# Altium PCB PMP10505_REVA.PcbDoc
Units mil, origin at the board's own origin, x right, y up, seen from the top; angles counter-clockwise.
Board outline 2750 x 2200 mil, 2 copper layers (Top Layer, Bottom Layer), stack 62 mil thick; 73 components, 28 nets, 117 pads, 15 vias.
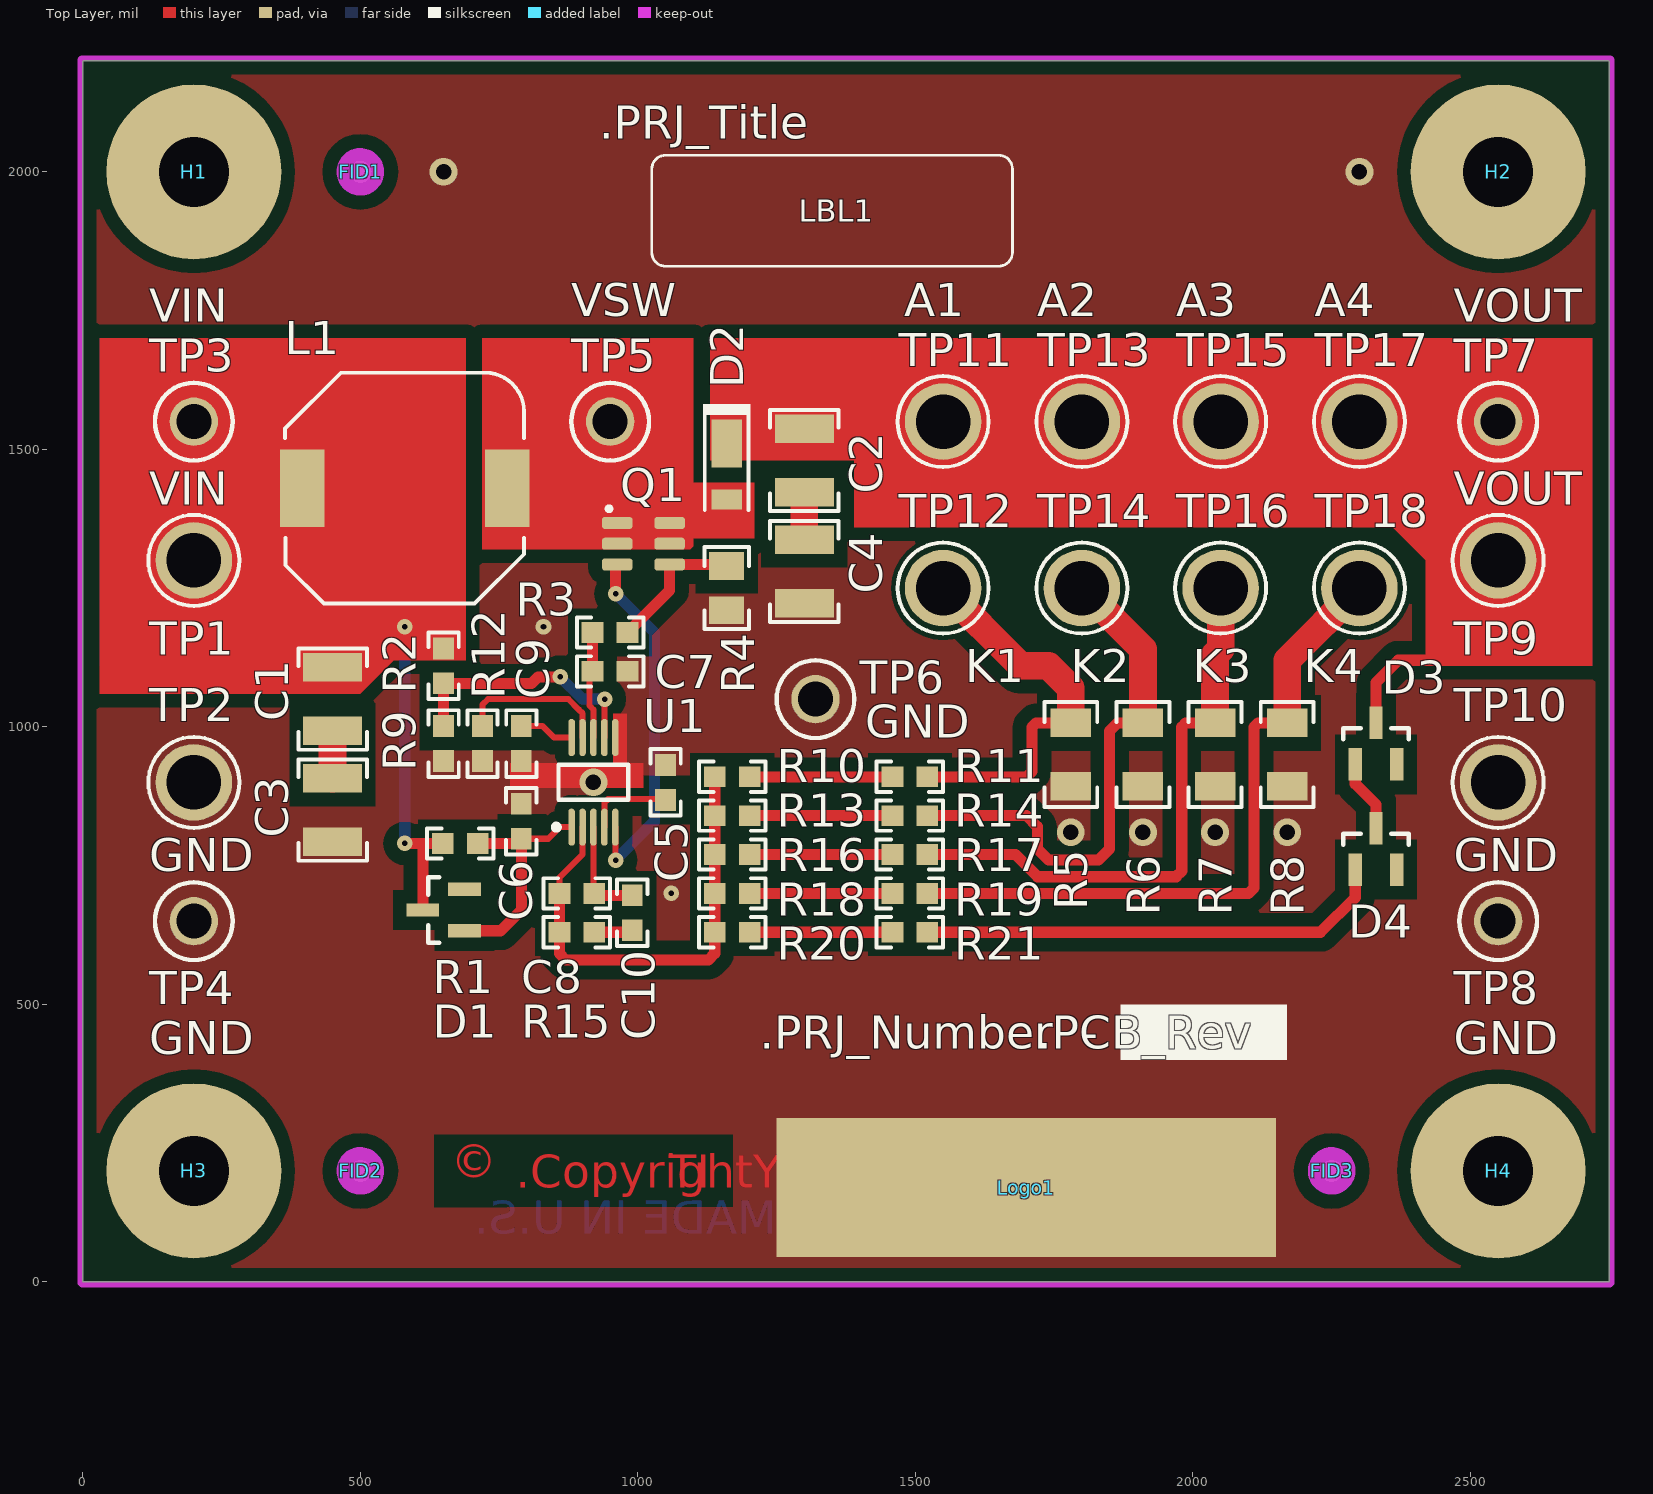
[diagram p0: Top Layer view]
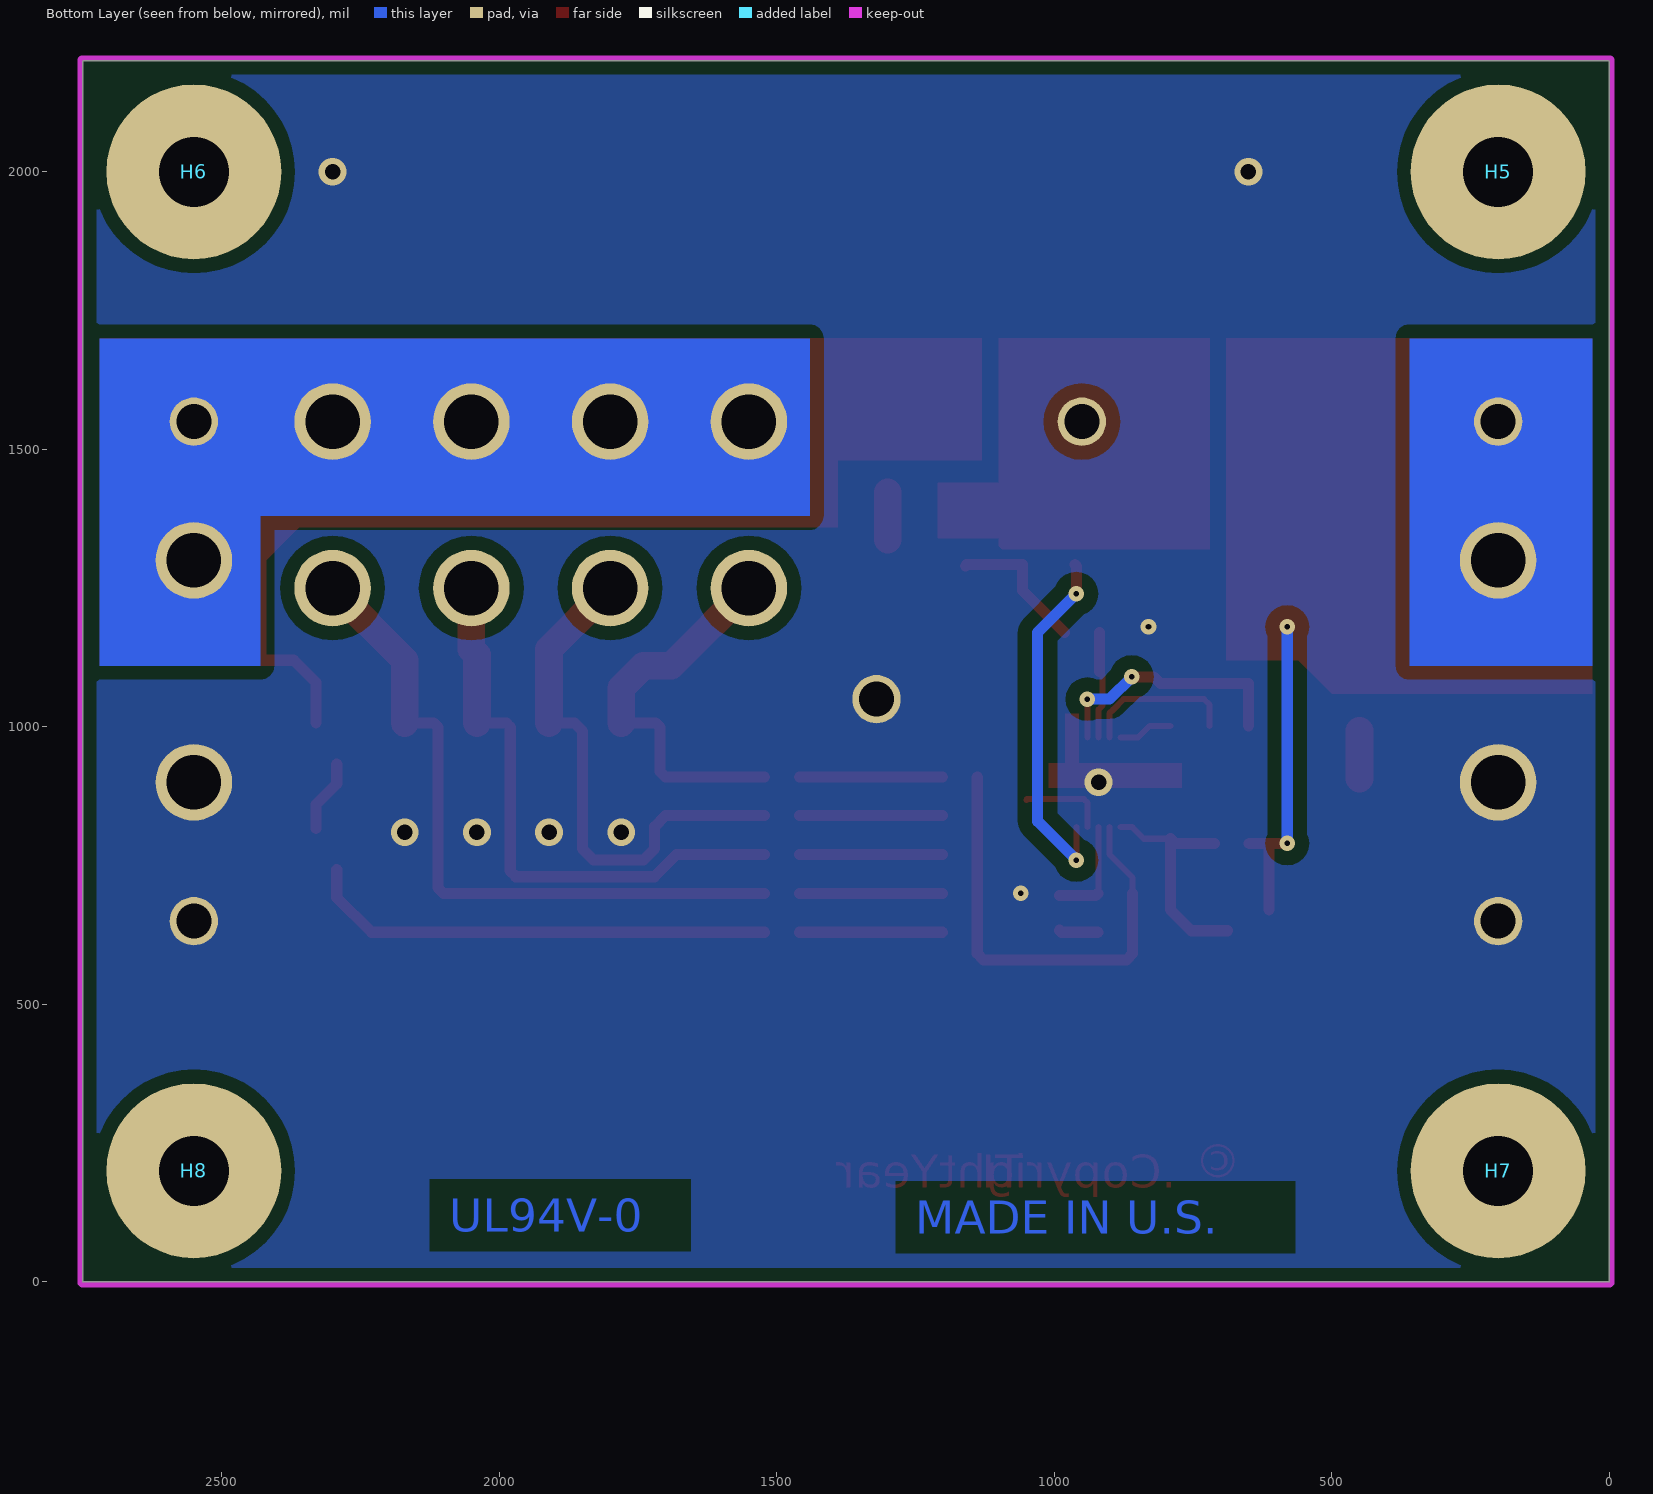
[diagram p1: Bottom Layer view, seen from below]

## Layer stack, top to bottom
Top Layer: signal copper 1.4
Dielectric: core 59.2, FR-4, Dk 4.8
Bottom Layer: signal copper 1.4

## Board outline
0,0 2750,0 2750,2200 0,2200

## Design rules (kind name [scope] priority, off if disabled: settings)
AcuteAngle [All] p1: minimum=4.50000000000000E+0001 checktracksonly=FALSE
AssemblyTestPointUsage [All] p1: valid=2
Clearance Clearance_BoardEdge_MountingHoles [OnCopper and InComponentClass('Mounting Holes') vs IsKeepOut] p1: gap=40
Clearance Clearance_BoardEdge_Poly [OnCopper and InPoly or IsRegion or IsFill vs IsKeepOut] p2: gap=25
Clearance Clearance_BoardEdge [OnCopper and Not InComponentClass('Logo') and not InComponentClass('FiducialMark') and not InRegion(1000,500,4000,800) and Not IsKeepout vs IsKeepOut] p3: gap=75
Clearance Clearance_Poly [InPolygon] p4: gap=25
Clearance [All] p5: gap=7.87
ComponentClearance ComponentClearance_Shunt [InComponentClass('Header') vs InComponentClass('Shunt')] p1: gap=0 collisioncheckmode=3 verticalgap=0 showdistances=FALSE
ComponentClearance ComponentClearance_MountingHoles_FiducialMarks [InComponentClass('Mounting Holes') vs InComponentClass('FiducialMark')] p2: gap=50 collisioncheckmode=3 verticalgap=10 showdistances=FALSE
ComponentClearance ComponentClearance_Logo [InComponentClass('Logo')] p3: gap=50 collisioncheckmode=3 verticalgap=10 showdistances=FALSE
ComponentClearance ComponentClearance_ScrewToNut [(HasFootprint('NY PMS 440 0025 PH')) vs (HasFootprint('Keystone_1902C'))] p4: gap=5 collisioncheckmode=3 verticalgap=10 showdistances=FALSE
ComponentClearance ComponentClearance_MountingHoles [InComponentClass('Mounting Holes')] p5: gap=250 collisioncheckmode=3 verticalgap=100000 showdistances=FALSE
ComponentClearance ComponentClearance_SmallPassives [HasFootprint('0201*') or HasFootprint('0402*') or HasFootprint('0508') or HasFootprint('0603*') or HasFootprint('0612') or HasFootprint('0805*') or HasFootprint('0815*') or HasFootprint('0830*') or HasFootprint('1206*') or HasFootprint('1210*') or HasFootprint('1808*') or HasFootprint('1812*') or HasFootprint('1825*') or HasFootprint('2010*') or HasFootprint('2220*') or HasFootprint('2225*') or HasFootprint('2512*') or HasFootprint('2728*') or HasFootprint('3518*') vs HasFootprint('0201*') or HasFootprint('0402*') or HasFootprint('0508') or HasFootprint('0603*') or HasFootprint('0612') or HasFootprint('0805*') or HasFootprint('0815*') or HasFootprint('0830*') or HasFootprint('1206*') or HasFootprint('1210*') or HasFootprint('1808*') or HasFootprint('1812*') or HasFootprint('1825*') or HasFootprint('2010*') or HasFootprint('2220*') or HasFootprint('2225*') or HasFootprint('2512*') or HasFootprint('2728*') or HasFootprint('3518*')] p6: gap=20 collisioncheckmode=3 verticalgap=10 showdistances=FALSE
ComponentClearance ComponentClearance_THtoSMT [IsThruComponent vs IsSMTComponent] p7: gap=100 collisioncheckmode=3 verticalgap=30 showdistances=FALSE
ComponentClearance ComponentClearance_THtoTH [IsThruComponent vs IsThruComponent] p8: gap=118.11 collisioncheckmode=3 verticalgap=30 showdistances=FALSE
ComponentClearance [All] p9: gap=40 collisioncheckmode=3 verticalgap=10 showdistances=FALSE
DiffPairsRouting [All] p1: maxlimit=100 minlimit=10 mostfreqgap=10 maxuncoupledlength=1000
FabricationTestPointUsage TestPointUsage [All] p1: valid=2 allowmultiple=FALSE
FabricationTestpoint Testpoint [All] p1: side=3 testpointundercomponent=TRUE minsize=40 maxsize=100 preferedsize=60 minholesize=0 maxholesize=40 preferedholesize=32 testpointgrid=1 allowsidetop=TRUE allowsidebottom=TRUE usegrid=TRUE gridtolerance=0.01
FanoutControl Fanout_LCC [IsLCC] p1: bgadir=Out bgaviamode=Centered fanoutstyle=Auto fanoutdirection=Alternating viagrid=1 // Fanout_LCC (Default Rule)
FanoutControl Fanout_BGA [IsBGA] p2: bgadir=Out bgaviamode=Centered fanoutstyle=Auto fanoutdirection=Alternating viagrid=1 // Fanout_BGA (Default Rule)
FanoutControl Fanout_Default [All] p4: bgadir=Out bgaviamode=Centered fanoutstyle=Auto fanoutdirection=Alternating viagrid=1 // Fanout_Default (Default Rule)
FanoutControl Fanout_Small [(CompPinCount < 5)] p5: bgadir=Out bgaviamode=Centered fanoutstyle=Auto fanoutdirection=OutThenIn viagrid=1 // Fanout_Small (Default Rule)
HoleSize [All] p1: absolutevalues=TRUE maxlimit=251 minlimit=8 maxpercent=80.000 minpercent=20.000
MinimumAnnularRing MinimumAnnularRing_ThermalPadVias [IsVia and InAnyComponent] p1: minimumring=5.91
MinimumAnnularRing [All] p2: minimumring=9
MinimumSolderMaskSliver MinimumSolderMaskSliver_Logo [InComponentClass('Logo') vs InComponentClass('Logo')] p1: minsoldermaskwidth=0.7
MinimumSolderMaskSliver [All] p2: minsoldermaskwidth=3.94
PlaneConnect [All] p1: planeconnectstyle=Direct reliefexpansion=10 reliefentries=4 reliefconductorwidth=10 reliefairgap=10
PolygonConnect [All] p1: connectstyle=Direct reliefconductorwidth=10 reliefentries=4 polygonreliefangle="90 Angle" airgapwidth=10
RoutingVias ThermalPadVias [IsVia and InAnyComponent] p1: holewidth=7.87 width=19.68 viastyle="Through Hole" minholewidth=7.87 minwidth=19.68 maxholewidth=12.99 maxwidth=23.62
RoutingVias [All] p2: holewidth=16 width=34 viastyle="Through Hole" minholewidth=7.87 minwidth=26 maxholewidth=40 maxwidth=65
SMDToCorner [All] p1: distance=30000
SilkToSilkClearance [All] p1: silktosilkclearance=5
SilkscreenOverComponentPads [All] p1: minsilkscreentomaskgap=5
SolderMaskExpansion [All] p1: expansion=1.97
Width [All] p1: maxlimit=100 minlimit=6 preferedwidth=10 checkconnectedcopper=TRUE
14 further rules are at their usual default settings.

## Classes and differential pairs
component class PMP10505_REVA: C1 C2 C3 C4 C5 C6 C7 C8 C9 C10 D1 D2 D3 D4 L1 Q1 R1 R2 R3 R4 R5 R6 R7 R8 R9 R10 R11 R12 R13 R14 R15 R16 R17 R18 R19 R20 R21 TP1 TP2 TP3 TP4 TP5 TP6 TP7 TP8 TP9 TP10 TP11 TP12 TP13 TP14 TP15 TP16 TP17 TP18 U1
component class Label: LBL1
component class AssemblyNote: ZZ1 ZZ2 ZZ3 ZZ4
component class FiducialMark: FID1 FID2 FID3
component class PMP10505_REVA_Hardware: FID1 FID2 FID3 H1 H2 H3 H4 H5 H6 H7 H8 LBL1 Logo1 ZZ1 ZZ2 ZZ3 ZZ4
component class Logo: Logo1
component class "Mounting Holes": H1 H2 H3 H4

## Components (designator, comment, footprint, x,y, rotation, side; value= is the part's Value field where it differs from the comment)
C1 "C3225X7S2A475K200AB" 1210 450,1050 r270 top
C2 "C3225X7S2A475K200AB" 1210 1300,1480 r270 top
C3 "C3225X7S2A475K200AB" 1210 450,850 r270 top
C4 "C3225X7S2A475K200AB" 1210 1300,1280 r270 top
C5 "GRM188R71C224KA01D" 0603 1050,900 r90 top
C6 "GRM188R72A104KA35D" 0603 790,830 r90 top
C7 "GRM188R71H331KA01D" 0603 950,1100 r0 top
C8 "GRM1885C1H101JA01D" 0603 890,700 r0 top
C9 "GRM188R71H103KA01D" 0603 790,970 r270 top
C10 "GRM188R71H472KA01D" 0603 990,665 r90 top
D1 "BZX84C20LT1G" SOT-23 650,670 r180 top
D2 "DFLS1200-7" powerDI123 1160,1460 r270 top
D3 "BZX84C43LT1G" SOT-23 2330,970 r90 top
D4 "BZX84C43LT1G" SOT-23 2330,780 r90 top
FID1 "Fiducial" Fiducial10-20 500,2000 r0 top
FID2 "Fiducial" Fiducial10-20 500,200 r0 top
FID3 "Fiducial" Fiducial10-20 2250,200 r0 top
H1 "NY PMS 440 0025 PH" "NY PMS 440 0025 PH" 200,2000 r0 top locked
H2 "NY PMS 440 0025 PH" "NY PMS 440 0025 PH" 2550,2000 r0 top locked
H3 "NY PMS 440 0025 PH" "NY PMS 440 0025 PH" 200,200 r0 top locked
H4 "NY PMS 440 0025 PH" "NY PMS 440 0025 PH" 2550,200 r0 top locked
H5 "1902C" Keystone_1902C 200,2000 r180 bottom locked
H6 "1902C" Keystone_1902C 2550,2000 r180 bottom locked
H7 "1902C" Keystone_1902C 200,200 r180 bottom locked
H8 "1902C" Keystone_1902C 2550,200 r180 bottom locked
L1 "MSS1038-224KLB" MSS1038 580,1430 r0 top
LBL1 "Size: 0.65\" x 0.20 \"" Label_650x200 1350,1930 r0 top
Logo1 "Texas Instruments" TI_Stacked_SolderMask_Small 1700,170 r0 top
Q1 "IRF5801TRPBF" TSOP-6 1010,1330 r0 top
R1 "CRCW060310R0JNEA" 0603 680,790 r180 top
R2 "CRCW0603100KFKEA" 0603 650,1110 r90 top
R3 "CRCW0603300RJNEA" 0603 950,1170 r0 top
R4 "CRCW08051R00FKEA" 0805_HV 1160,1250 r90 top
R5 "CRCW120619R1FKEA" 1206 1780,950 r90 top
R6 "CRCW120619R1FKEA" 1206 1910,950 r90 top
R7 "CRCW120619R1FKEA" 1206 2040,950 r90 top
R8 "CRCW120619R1FKEA" 1206 2170,950 r90 top
R9 "CRCW06032K49FKEA" 0603 650,970 r90 top
R10 "CRCW060310K0JNEA" 0603 1170,910 r0 top
R11 "CRCW060351R0JNEA" 0603 1490,910 r0 top
R12 "CRCW060331K6FKEA" 0603 720,970 r90 top
R13 "CRCW060310K0JNEA" 0603 1170,840 r0 top
R14 "CRCW060351R0JNEA" 0603 1490,840 r0 top
R15 "CRCW06038K20JNEA" 0603 890,630 r180 top
R16 "CRCW060310K0JNEA" 0603 1170,770 r0 top
R17 "CRCW060351R0JNEA" 0603 1490,770 r0 top
R18 "CRCW060310K0JNEA" 0603 1170,700 r0 top
R19 "CRCW060351R0JNEA" 0603 1490,700 r0 top
R20 "CRCW060347K0JNEA" 0603 1170,630 r0 top
R21 "CRCW060351R0JNEA" 0603 1490,630 r0 top
TP1 "VIN" Keystone1598-2 200,1300 r0 top
TP2 "GND" Keystone1598-2 200,900 r0 top
TP3 "VIN" Keystone5010 200,1550 r0 top
TP4 "GND" Keystone5011 200,650 r0 top
TP5 "VSW" Keystone5010 950,1550 r0 top
TP6 "GND" Keystone5011 1320,1050 r0 top
TP7 "VOUT" Keystone5010 2550,1550 r0 top
TP8 "GND" Keystone5011 2550,650 r0 top
TP9 "VOUT" Keystone1598-2 2550,1300 r0 top
TP10 "GND" Keystone1598-2 2550,900 r0 top
TP11 "A1" Keystone1598-2 1550,1550 r0 top
TP12 "K1" Keystone1598-2 1550,1250 r0 top
TP13 "A2" Keystone1598-2 1800,1550 r0 top
TP14 "K2" Keystone1598-2 1800,1250 r0 top
TP15 "A3" Keystone1598-2 2050,1550 r0 top
TP16 "K3" Keystone1598-2 2050,1250 r0 top
TP17 "A4" Keystone1598-2 2300,1550 r0 top
TP18 "K4" Keystone1598-2 2300,1250 r0 top
U1 "LM5020MM-2/NOPB" MUB10A_N 920,900 r90 top
ZZ1 "This Assembly Note is for PCB labels only" AssemblyNoteLabel 185,3938 r0 top
ZZ2 "These assemblies are ESD sensitive, ESD precautions shall be observed." AssemblyNote 185,3829.11 r0 top
ZZ3 "These assemblies must be clean and free from flux and all contaminants. Use of no clean flux is not acceptable." AssemblyNote 185,3740.56 r0 top
ZZ4 "These assemblies must comply with workmanship standards IPC-A-610 Class 2, unless otherwise specified." AssemblyNote 185,3652 r0 top

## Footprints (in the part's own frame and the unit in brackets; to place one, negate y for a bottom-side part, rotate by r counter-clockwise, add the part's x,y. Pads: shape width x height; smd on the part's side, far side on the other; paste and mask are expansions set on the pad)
0603 [mm] "0603 from SM-752 data"
  rect 1x0.95 smd: 1(-0.8,0) 2(0.8,0)
  silkscreen extent -1.52,-0.69 1.52,0.69, body extent -0.87,-0.47 0.87,0.47, height 0.85
0805_HV [mil] "0805 with 30mil clearance between pads"
  rect 50x63 smd: 1(-40,0) 2(40,0)
  silkscreen extent -74,-40 74,40, body extent -43,-29 43,29, height 43
1206 [mm] "1206 from SM-752 data"
  rect 1.3x1.85 smd: 1(-1.45,0) 2(1.45,0)
  silkscreen extent -2.4,-1.21 2.4,1.21, body extent -1.7,-0.9 1.7,0.9, height 1.35
1210 [mm] "1210 from SM-752 data"
  rect 1.3x2.7 smd: 1(-1.45,0) 2(1.45,0)
  silkscreen extent -2.32,-1.57 2.32,1.57, body extent -1.7,-1.35 1.7,1.35, height 1.35
AssemblyNote [mil] "Assembly Note"
AssemblyNoteLabel [mil] "Assembly Note for PCB Labels"
Fiducial10-20 [mm]
  round 1 smd paste-0.5 mask+0.5: 1(0,0)
  Top Layer keep-out circle w1.178: c0,0 r0.5
Keystone1598-2 [mm] "Triple Turret"
  round 3.5 hole 2.5: 1(0,0)
  silkscreen extent -2.08,-2.08 2.08,2.08, body extent -1.6,-1.6 1.59,1.6, height 7.72
Keystone5010 [mil] "Keystone Multipurpose loops"
  round 87 hole 63: 1(0,0)
  silkscreen extent -70,-70 70,70, body extent -63,-63 63,62, height 319
Keystone5011 [mil] "Keystone Multipurpose loops"
  round 87 hole 63: 1(0,0)
  silkscreen extent -70,-70 70,70, body extent -63,-63 63,62, height 319
Keystone_1902C [mil] "Hex Standoff, 4-40 threaded, nylon"
  body extent -145,-126 146,126, height 501
Label_650x200 [mil] "Thermal Transfer Label"
  silkscreen extent -325,-100 325,100, body extent -326,-101 326,101, height 1
MSS1038 [mil]
  rect 80x140 smd: 1(-185,0) 2(185,0)
  silkscreen extent -216,-208 215,208, body extent -203,-201 203,201, height 158
MUB10A_N [mm] "TSSOP, 10-Leads, Body 3x3mm, Pitch 0.5mm, IPC Medium Density"
  oval 1.7x0.3 smd: 1(-2.05,1) 2(-2.05,0.5) 3(-2.05,0) 4(-2.05,-0.5) 5(-2.05,-1) 6(2.05,-1) 7(2.05,-0.5) 8(2.05,0) 9(2.05,0.5) 10(2.05,1)
  silkscreen extent -2.17,-1.6 0.8,1.82, body extent -1.6,-1.6 1.6,1.6, height 1.09
"NY PMS 440 0025 PH" [mm] "4-40 nylon screw and mounting hole"
  round 8 hole 3.2: 1(0,0)
  body extent -3.3,-3.3 3.3,3.3, height 2.69
powerDI123 [mm] "Diodes Inc recommended land pattern, document number DS30628 Rev. 6-2"
  rect 2.2x1.4 smd: 1(-1.275,0)
  rect 0.9x1.4 smd: 2(1.275,0)
  silkscreen extent -3.1,-1.09 1.76,1.09, body extent -2.38,-0.97 1.52,0.96, height 1
SOT-23 [mm] "SOT23, 3-Leads, Body 2.9x1.3mm, Pitch 0.95mm, Lead Span 2.5mm, IPC Medium Density"
  rect 1.5x0.6 smd: 1(-0.95,0.95) 2(-0.95,-0.95) 3(0.95,0)
  silkscreen extent 0.2,-1.5 0.7,1.5, body extent -1.16,-1.45 1.21,1.45, height 1
TI_Stacked_SolderMask_Small [mil]
  rect 900x250 smd paste-125 mask-125: 0(0,0)
TSOP-6 [mm] "TSOP, 6-Leads, Body 3.1x1.7mm (max), Pitch 0.95mm, IPC Medium Density"
  rrect50% 1.4x0.55 smd: 1(-1.2,0.95) 2(-1.2,0) 3(-1.2,-0.95) 4(1.2,-0.95) 5(1.2,0) 6(1.2,0.95)
  silkscreen extent -1.67,1.5 -1.48,1.7, body extent -1.37,-1.5 1.38,1.5, height 1.05

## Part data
C1 C2 C3 C4: "CAP, CERM, 4.7uF, 100V, +/-10%, X7S, 1210"
C5: "CAP, CERM, 0.22uF, 16V, +/-10%, X7R, 0603"
C6: "CAP, CERM, 0.1uF, 100V, +/-10%, X7R, 0603"
C7: "CAP, CERM, 330pF, 50V, +/-10%, X7R, 0603"
C8: "CAP, CERM, 100pF, 50V, +/-5%, C0G/NP0, 0603"
C9: "CAP, CERM, 0.01uF, 50V, +/-10%, X7R, 0603"
C10: "CAP, CERM, 4700pF, 50V, +/-10%, X7R, 0603"
D1: "Diode, Zener, 20V, 225mW, SOT-23"
D2: "Diode, Schottky, 200V, 1A, PowerDI123"
D3 D4: "Diode, Zener, 43V, 225mW, SOT-23"
FID1 FID2 FID3: "Fiducial mark.  There is nothing to buy or mount."
H1 H2 H3 H4: "Machine Screw, Round, #4-40 x 1/4, Nylon, Philips panhead"
H5 H6 H7 H8: "Standoff, Hex, 0.5\"L #4-40 Nylon"
L1: "Inductor, Shielded Drum Core, Ferrite, 220uH, 0.97A, 0.76 ohm, SMD"
LBL1: library part THT-14-423-10, "Thermal Transfer Printable Labels, 0.650\" W x 0.200\" H - 10,000 per roll"
Logo1: library part TI_Logo, "Texas Instrument Corporate Signature"
Q1: "MOSFET, N-CH, 200V, 0.6A, TSOP-6"
R1: "RES, 10 ohm, 5%, 0.1W, 0603"
R2: "RES, 100k ohm, 1%, 0.1W, 0603"
R3: "RES, 300 ohm, 5%, 0.1W, 0603"
R4: "RES, 1.00 ohm, 1%, 0.125W, 0805"
R5 R6 R7 R8: "RES, 19.1 ohm, 1%, 0.25W, 1206"
R9: "RES, 2.49k ohm, 1%, 0.1W, 0603"
R10 R13 R16 R18: "RES, 10k ohm, 5%, 0.1W, 0603"
R11 R14 R17 R19 R21: "RES, 51 ohm, 5%, 0.1W, 0603"
R12: "RES, 31.6k ohm, 1%, 0.1W, 0603"
R15: "RES, 8.2k ohm, 5%, 0.1W, 0603"
R20: "RES, 47k ohm, 5%, 0.1W, 0603"
TP1 TP2 TP9 TP10 TP11 TP12 TP13 TP14 TP15 TP16 TP17 TP18: library part 1598-2, "Terminal, Turret, TH, Triple"
TP3 TP5 TP7: library part 5010, "Test Point, Multipurpose, Red, TH"
TP4 TP6 TP8: library part 5011, "Test Point, Multipurpose, Black, TH"
U1: "100V Current Mode PWM Controller, 10-pin MSOP, Pb-Free"
ZZ1: library part AssemblyNoteLabel
ZZ2 ZZ3 ZZ4: library part AssemblyNote

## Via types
v1: diameter 28, hole 10, Top Layer to Bottom Layer, 8 vias
v2: diameter 50, hole 28, Top Layer to Bottom Layer, 7 vias

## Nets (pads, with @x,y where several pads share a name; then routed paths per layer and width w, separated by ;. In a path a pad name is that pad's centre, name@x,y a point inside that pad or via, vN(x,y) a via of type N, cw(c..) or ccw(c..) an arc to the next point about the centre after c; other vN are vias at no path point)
CMP: C10.1 R15.1 | length 70
  Top Layer w20: R15.1 986.5,630 C10.1
COMP: C8.2 C10.2 U1.3 | length 189.9
  Top Layer w11: U1.3 920,701.5 C8.2
  Top Layer w20: C8.2 925,696.5 C10.2
CS: C7.1 R3.1 U1.8 | length 194.8
  Top Layer w11: C7.1 912.63,1094.12 912.63,1038.66 920,1031.29 U1.8
  Top Layer w20: C7.1 R3.1
CS1: Q1.4 R3.2 R4.2 | length 257.8
  Top Layer w20: R3.2 1057.24,1245.75 Q1.4 1157.4,1292.6 R4.2
FB: C8.1 R10.1 R13.1 R15.2 R16.1 R18.1 R20.1 U1.2 | length 853.1
  Top Layer w11: C8.1 858.5,728.5 900.31,770.31 U1.2
  Top Layer w20: C8.1 R15.2 858.5,591.5 870,580 1127.01,580 1138.5,591.5 R20.1 R18.1 R16.1 R13.1 R10.1
FB1: R10.2 R11.1 | length 257
  Top Layer w20: R10.2 R11.1
FB2: R13.2 R14.1 | length 257
  Top Layer w20: R13.2 R14.1
FB3: R16.2 R17.1 | length 257
  Top Layer w20: R16.2 R17.1
FB4: R18.2 R19.1 | length 257
  Top Layer w20: R18.2 R19.1
FB5: R20.2 R21.1 | length 257
  Top Layer w20: R20.2 R21.1
GND: C3.2 C4.2 C5.2 C6.2 C7.2 C9.2 Logo1.0 R4.1 R5.1 R6.1 R7.1 R8.1 R9.1 R12.1 TP2.1 TP4.1 TP6.1 TP8.1 TP10.1 U1.6
  other v1: 1060,700 830,1180
  other v2: 1780,810 1910,810 2040,810 2170,810 920,900 650,2000 2300,2000
NetC1_2: C1.2 C3.1 | length 85.8
  Top Layer w50: C3.1 C1.2
NetC2_2: C2.2 C4.1 | length 85.8
  Top Layer w50: C4.1 C2.2
OUT: Q1.3 U1.5 | length 651.3
  Top Layer w11: U1.5 959.37,760.63 v1(960,760)
  Top Layer w20: v1(960,1240) 960,1289.84 Q1.3
  Bottom Layer w20: v1(960,760) 1030,830 1030,1170 v1(960,1240)
RT: R12.2 U1.9 | length 277.4
  Top Layer w11: R12.2 720,1040 730,1050 875,1050 893.75,1031.25 893.75,1030.84 900.31,1024.28 U1.9
SS: C9.1 U1.10 | length 99.2
  Top Layer w11: C9.1 828.5,1001.5 849.29,980.71 U1.10
UVLO: R2.1 R9.2 U1.7 | length 457.8
  Top Layer w11: U1.7 939.68,1049.68 v1(940,1050)
  Top Layer w20: R9.2 R2.1 808.5,1078.5 820,1090 v1(860,1090)
  Bottom Layer w20: v1(860,1090) 900,1050 v1(940,1050)
VCC: C5.1 U1.4 | length 157.7
  Top Layer w11: U1.4 939.68,863.19 946.5,870 1048.5,870 C5.1
VIN: C1.1 D1.3 L1.1 R1.2 R2.2 TP1.1 TP3.1 | length 856.3
  Top Layer w20: C1.1 450,1160 470,1180 v1(580,1180) 611.5,1180 R2.2 ; v1(580,790) 614.25,790 ; D1.3 612.6,788.35 614.25,790 ; R1.2 614.25,790
  Bottom Layer w20: v1(580,790) v1(580,1180)
VINF: C6.1 D1.1 R1.1 U1.1 | length 427.9
  Top Layer w11: C6.1 838.5,798.5 859.29,819.29 U1.1
  Top Layer w20: D1.1 752.6,632.6 790,670 C6.1 781.5,790 R1.1
VOUT: C2.1 D2.1 D3.3 TP7.1 TP9.1 TP11.1 TP13.1 TP15.1 TP17.1 | length 199.2
  Top Layer w20: D3.3 2330,1080 2370,1120 2440,1120
VS1: R5.2 R11.2 TP12.1 | length 713.1
  Top Layer w20: R11.2 1700,910 1710,920 1710,1000 1717.09,1007.09 R5.2
  Top Layer w50: TP12.1 1690,1110 1740,1110 1780,1070 R5.2
VS2: R6.2 R14.2 TP14.1 | length 960.5
  Top Layer w20: R14.2 1700,840 1720,820 1720,780 1740,760 1830,760 1850,780 1850,992.76 1864.33,1007.09 R6.2
  Top Layer w50: TP14.1 1910,1140 R6.2
VS3: R7.2 R17.2 TP16.1 | length 1049.2
  Top Layer w20: R17.2 1680,770 1720,730 1970,730 1980,740 1980,1000 1987.09,1007.09 R7.2
  Top Layer w50: R7.2 2040,1130 2050,1140 TP16.1
VS4: R8.2 R19.2 TP18.1 | length 1242.3
  Top Layer w20: R19.2 2100,700 2110,710 2110,1000 2117.09,1007.09 R8.2
  Top Layer w50: R8.2 2170,1120 TP18.1
VS5: D4.1 R21.2 | length 847
  Top Layer w20: R21.2 2230,630 2292.6,692.6 D4.1
VSW: D2.2 L1.2 Q1.1 Q1.2 Q1.5 Q1.6 TP5.1
VZ: D3.1 D4.3 | length 130.7
  Top Layer w20: D3.1 2292.6,897.4 2330,860 D4.3
pads on no net: D1.2 D3.2 D4.2 FID1.1 FID2.1 FID3.1 H1.1 H2.1 H3.1 H4.1

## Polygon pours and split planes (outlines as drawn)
GND on Bottom Layer "Bottom Layer-GND" (solid, remove dead copper, pour order 2): 0,0 0,2200 2750,2200 2750,0 0,0
GND on Top Layer "Top Layer-GND" (solid, remove dead copper, pour order 4): 0,0 0,2200 2750,2200 2750,0 0,0

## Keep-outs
Keep-Out Layer:
  lines w10: -5,0 ccw(c0,0) 0,-5 ; -5,0 ccw(c0,0) 0,-5 ; -5,0 ccw(c0,0) 0,-5 ; -5,0 ccw(c0,0) 0,-5 ; -5,0 ccw(c0,0) 0,-5 ; -5,0 ccw(c0,0) 0,-5 ; -5,0 -5,2200 cw(c0,2200) 0,2205 2750,2205 cw(c2750,2200) 2755,2200 2755,0 cw(c2750,0) 2750,-5 0,-5 ; -5,3450 cw(c0,3450) 0,3455 ; -5,3450 cw(c0,3450) 0,3455 ; -5,3450 cw(c0,3450) 0,3455 ; -5,3450 cw(c0,3450) 0,3455 ; -5,3450 cw(c0,3450) 0,3455 ; 4950,-5 ccw(c4950,0) 4955,0 ; 4950,-5 ccw(c4950,0) 4955,0 ; 4950,-5 ccw(c4950,0) 4955,0 ; 4950,-5 ccw(c4950,0) 4955,0 ; 4950,-5 ccw(c4950,0) 4955,0 ; 4950,3455 cw(c4950,3450) 4955,3450 ; 4950,3455 cw(c4950,3450) 4955,3450 ; 4950,3455 cw(c4950,3450) 4955,3450 ; 4950,3455 cw(c4950,3450) 4955,3450 ; 4950,3455 cw(c4950,3450) 4955,3450
  text ".Layer_Name" at 577,-858.49 h60

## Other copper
Top Layer:
  rectangle net GND: 955,920 980,1024.02
  rectangle net GND: 770,890 1010,935
  region net VIN: 30,1700 690,1700 690,1120 560,1120 500,1060 30,1060
  region net VSW: 720,1700 1100,1700 1100,1440 1210,1440 1210,1340 1100,1340 1100,1325.35 1094.65,1320 720,1320
  region net VOUT: 1130,1700 2720,1700 2720,1110 2420,1110 2420,1300 2360,1360 1390,1360 1390,1480.13 1130,1480.13
  text ".CopyrightYear" at 780,170 h60
  text "TI" at 1056,170 h60
  text "©" at 663,166.48 h105
  text ".Layer_Name" at 577,-858.49 h60
Bottom Layer:
  rectangle net VIN: 30,1110 360,1700
  rectangle net VOUT: 2430,1110 2720,1700
  rectangle net VOUT: 1440,1380 2440,1700
  text ".VersionControl_RevNumber" at 2510,2420 h60
  text "SVN:" at 2789,2420 h60
  text "UL94V-0" at 2090,90 h60
  text "MADE IN U.S." at 1250,86.5 h60
  text ".Layer_Name" at 577,-858.49 h60

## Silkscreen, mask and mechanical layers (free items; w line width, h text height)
Top Overlay:
  region: 2170,500 1870,500 1870,400 2170,400
  text ".PRJ_Title" at 930,2060 h60
  text ".PRJ_Number" at 1220,420 h60
  text ".PCB_Rev" at 1720,420 h60
  text "-" at 1800,420.01 h60
  text ".Layer_Name" at 577,-858.49 h60
Bottom Overlay:
  text ".Layer_Name" at 577,-858.49 h60
Top Paste:
  text ".Layer_Name" at 577,-858.49 h60
Bottom Paste:
  text ".Layer_Name" at 577,-858.49 h60
Top Solder:
  text ".Layer_Name" at 577,-858.49 h60
  text ".Layer_Name" at 577,-858.49 h60
Bottom Solder:
  text ".Layer_Name" at 577,-858.49 h60
Drill Guide:
  text ".Layer_Name" at 577,-858.49 h60
M1 Board Outline:
  the board outline again, w10
  text ".Layer_Name" at 577,-858.49 h60
M2 Board Dimensions:
  rectangle: 125,-410.5 500,-285.5
  rectangle: 0,-285.5 125,-160.5
  lines w7: 0,-285.5 1000,-285.5 ; 125,-410.5 125,-160.5 ; 250,-410.5 250,-160.5 ; 500,-410.5 500,-160.5 ; 750,-410.5 750,-160.5 ; 0,-410.5 0,-160.5 1000,-160.5 1000,-410.5 0,-410.5
  text ".Layer_Name" at 577,-858.49 h60
M3 3D STEP Top:
  text ".Layer_Name" at 577,-858.49 h60
M4 3D STEP Bottom:
  text ".Layer_Name" at 577,-858.49 h60
M5 Assembly Top:
  lines w10: -292,-930.17 6308,-930.17 ; -292,-726.83 6310,-726.83 ; -292,-523.5 -292,-1133.5 3713,-1133.5 6310,-1133.5 6310,-523.5 -291.5,-523.5 -291.5,-1133.5 1284,-1133.5 ; 2173,-1133.5 2173,-523.5 ; 3440,-726.83 3440,-523.5 ; 4280,-726.83 4280,-523.5 ; 4902,-1140 4902,-937.17
  text "COMPONENTS MARKED 'DNP' SHOULD NOT BE POPULATED." at 1153.5,-318.5 h60
  text "ASSEMBLY VARIANT:" at 1153,-434 h60
  text ".VariantName" at 2189,-434 h60
  text "PCB VIEWED FROM TOP SIDE" at -228.5,-655.67 h60
  text "BOARD #:" at 2248,-655.67 h60
  text ".PRJ_Number" at 2793.5,-655.67 h60
  text "REV:" at 3638,-655.67 h60
  text ".PCB_Rev" at 3929.5,-655.67 h60
  text "SVN REV:" at 4476,-655.67 h60
  text ".VersionControl_RevNumber" at 4982,-655.67 h60
  text "IGNORE ->" at -228.5,-858.49 h60
  text "PLOT NAME =" at -228.5,-1064.34 h60
  text ".plot_File_Name" at 577,-1064.34 h60
  text "GENERATED    :" at 2250,-1064.34 h60
  text ".Print_Date" at 3119.5,-1064.34 h60
  text ".Print_Time" at 3848.5,-1064.34 h60
  text "TEXAS INSTRUMENTS" at 5113,-1064.34 h60
M6 Assembly Bottom:
  lines w10: -292.5,-727.33 6309.5,-727.33 ; -290.5,-930.67 6309.5,-930.67 ; 1115.5,-1140.5 1115.5,-937.67 ; 1737.5,-727.33 1737.5,-524 ; 2577.5,-727.33 2577.5,-524 ; 3844.5,-1134 3844.5,-524 ; 4733.5,-1134 6309,-1134 6309,-524 -292.5,-524 -292.5,-1134 2304.5,-1134 6309.5,-1134 6309.5,-524
  text "COMPONENTS MARKED 'DNP' SHOULD NOT BE POPULATED." at 6102,-318 h60
  text ".VariantName" at 5058,-434 h60
  text "ASSEMBLY VARIANT:" at 6097,-434 h60
  text ".VersionControl_RevNumber" at 1035.5,-656.17 h60
  text "SVN REV:" at 1541.5,-656.17 h60
  text ".PCB_Rev" at 2088,-656.17 h60
  text "REV:" at 2379.5,-656.17 h60
  text ".PRJ_Number" at 3224,-656.17 h60
  text "BOARD #:" at 3769.5,-656.17 h60
  text "PCB VIEWED FROM BOTTOM SIDE" at 6246,-656.17 h60
  text "IGNORE ->" at 2547.85,-858.49 h60
  text "TEXAS INSTRUMENTS" at 904.5,-1064.84 h60
  text ".Print_Time" at 2169,-1064.84 h60
  text ".Print_Date" at 2898,-1064.84 h60
  text "GENERATED    :" at 3767.5,-1064.84 h60
  text ".plot_File_Name" at 5440.5,-1064.84 h60
  text "PLOT NAME =" at 6246,-1064.84 h60
M9 Title Sheet:
  drawing of 57 lines, arcs and shapes, not listed
  text "1" at 739.84,8036.5 h70
  text "2" at 3235.5,8036.5 h70
  text "3" at 5724.84,8036.5 h70
  text "4" at 8231.51,8036.5 h70
  text "5" at 10730.5,8036.5 h70
  text "6" at 13235.5,8036.5 h70
  text "A" at -416.5,6893.5 h70
  text "A" at 14383.5,6893.5 h70
  text "B" at -416.5,4513.5 h70
  text "B" at 14383.5,4513.5 h70
  text "C" at -416.5,2138.5 h70
  text "C" at 14383.5,2138.5 h70
  text "PROJECT TITLE:" at 11343.5,277.5 h45
  text ".PRJ_Title" at 11393.5,144.17 h70
  text "DESIGNED FOR:" at 11343.5,-23.5 h45
  text ".PRJ_Customer" at 11393.5,-163.5 h70
  text "D" at -416.5,-231.5 h70
  text "D" at 14383.5,-231.5 h70
  text "FILE NAME:" at 11343.5,-323.5 h45
  text ".PCB_File_Name_No_Path" at 11393.5,-443.5 h70
  text "Texas Instruments (TI) and/or its licensors do not warrant the accuracy or completeness of this specification" at 6374,-605.34 h45
  text "ENGINEER:" at 11343.5,-613.5 h45
  text "LAYOUT BY:" at 12848.5,-613.5 h45
  text "or any information contained therein. TI and/or its licensors do not warrant that this design will meet" at 6329.01,-718 h45
  text ".PRJ_Engineer" at 11393.5,-768.49 h70
  text ".PCB_Layout" at 12899,-768.49 h70
  text "the specifications, will be suitable for your application or fit for any particular purpose, or will operate in" at 6329.01,-830.67 h45
  text ".Layer_Name" at 577,-858.49 h60
  text "ALTIUM DESIGNER VERSION:" at 12848.5,-923.5 h45
  text "an implementation. TI and/or its licensors do not warrant that the design is production worthy. You should" at 6329.01,-943.33 h45
  text "completely validate and test your design implementation to confirm the system functionality for your application." at 6374,-1056 h45
  text ".print_Scale" at 11393.5,-1056.83 h70
  text ".Application_BuildNumber" at 12899,-1056.83 h70
  text "1" at 739.84,-1263.5 h70
  text "2" at 3235.5,-1263.5 h70
  text "3" at 5724.84,-1263.5 h70
  text "4" at 8231.51,-1263.5 h70
  text "5" at 10730.5,-1263.5 h70
  text "6" at 13235.5,-1263.5 h70
M10 Fab Notes:
  drawing of 185 lines, arcs and shapes, not listed
  text "DESIGN INFORMATION" at 12381.02,5910 h60
  text "MIN. TRACK WIDTH:" at 11736.46,5730 h60
  text "8" at 12832.7,5730 h60
  text "MIL" at 12987.46,5730 h60
  text "MIN. CLEARANCE:" at 11736.46,5598 h60
  text "0.2" at 12772.7,5598 h60
  text "mm" at 12987.46,5598 h60
  text "MIN. VIA PAD SIZE:" at 11736.46,5466 h60
  text "24" at 12802.71,5466 h60
  text "MIL" at 12987.46,5466 h60
  text "0.05mm (2MIL)" at 12431.46,5324.29 h60
  text "MINIMUM ANNULAR RING" at 11407.23,5320 h60
  text "EXTERNAL" at 13139.46,5320 h60
  text "PER" at 11607.23,5202 h60
  text "IPC-D-275 CLASS 2 LEVEL C" at 11827.23,5202 h60
  text "MIL, HOLES" at 13315.46,5089.71 h60
  text "+/-" at 12923,5089 h60
  text "+/-" at 13777,5089 h60
  text "REGISTRATION TOLERANCES:" at 11407.23,5084 h60
  text "METAL" at 12607,5084 h60
  text "5" at 13183.2,5084 h60
  text "3" at 14016.2,5084 h60
  text "MIL" at 14132.46,5084 h60
  text "MATERIAL:" at 11332.46,4874.54 h60
  text "FR-4 High Tg" at 12318.9,4734.21 h60
  text "FR-408" at 11753.46,4725.64 h60
  text "X" at 12165.46,4725.64 h60
  text "OTHER" at 13241.46,4725.64 h60
  text "62 MIL (1.6mm) +/-10%" at 12073.56,4562.92 h60
  text "THICKNESS:" at 11407.23,4558.64 h60
  text "X" at 11945.4,4558.64 h60
  text "OTHER" at 13358.46,4558.64 h60
  text "TOLERANCE:" at 11407.23,4400.64 h60
  text "X" at 12246.53,4400.64 h60
  text "ANSI IPC-6012 TYPE 3 CLASS 2" at 12433.48,4400.64 h60
  text "OTHER +/-" at 12433.46,4244.64 h60
  text "BOW & TWIST:" at 11407.23,4087.64 h60
  text "X" at 12246.53,4087.64 h60
  text "ANSI IPC-6012 TYPE 3 CLASS 2" at 12433.48,4087.64 h60
  text "OTHER +/-" at 12433.46,3929.13 h60
  text "DRILLING:" at 11332.46,3790.64 h60
  text "REFERENCE:" at 11407.23,3673.64 h60
  text "X" at 12055.46,3673.64 h60
  text "AS SHOWN" at 12242.46,3673.64 h60
  text "X" at 12956.46,3673.64 h60
  text "NC_DRILL FILES" at 13093.46,3673.64 h60
  text "PTH MIN COPPER THICKNESS:" at 11407.23,3515.64 h60
  text "X" at 12757.46,3515.64 h60
  text "1MIL" at 12894.46,3515.64 h60
  text "OTHER" at 13391.46,3515.64 h60
  text "BOARD FINISH:" at 11332.46,3356.64 h60
  text "SILKSCREEN:" at 11487.68,3238.64 h60
  text "X" at 12436.46,3238.64 h60
  text "TOP" at 12562.46,3238.64 h60
  text "BOTTOM" at 13073.46,3238.64 h60
  text "SILKSCREEN COLOR:" at 11487.68,3071.64 h60
  text "X" at 12435.42,3071.64 h60
  text "WHITE" at 12562.46,3071.64 h60
  text "OTHER" at 13073.46,3071.64 h60
  text "SOLDER RESIST COLOR:" at 11487.68,2901.64 h60
  text "X" at 12055.42,2742.44 h60
  text "GREEN" at 12182.46,2742.44 h60
  text "BLUE" at 12773.46,2742.44 h60
  text "OTHER" at 13311.46,2742.44 h60
  text "IMMERSION GOLD (ENIG)" at 12393.46,2553.92 h60
  text "ENEPIG" at 13731,2550.64 h60
  text "SURFACE FINISH:" at 11332.46,2549.64 h60
  text "X" at 11500,2395 h60
  text "IMM. TIN/SILVER OR EQUIV" at 11662,2392.64 h60
  text "OTHER" at 13093.46,2392.64 h60
  text "ARRAY/PANEL:" at 11332.46,2213.64 h60
  text "X" at 12205,2210 h60
  text "CUT AND TRIM PER MECH LAYER 1" at 12393.46,2209.35 h60
  text "N.C. ROUTE" at 12393.46,2057.64 h60
  text "V. SCORE" at 13259.46,2057.64 h60
  text "CERTIFICATION:" at 11332.46,1920.64 h60
  text "MATERIALS AND WORKMANSHIP FOR ALL PCBS" at 12057.46,1920.64 h60
  text "TO MEET OR EXCEED THE REQUIREMENTS OF:" at 12057.46,1822.64 h60
  text "X" at 11683.96,1686.13 h60
  text "ANSI IPC-A-600F CLASS ->" at 11822.96,1686.13 h60
  text "X" at 13462.02,1686.13 h60
  text "2" at 13580.96,1686.14 h60
  text "1" at 13265.96,1684.64 h60
  text "3" at 13934.96,1684.64 h60
  text "X" at 11686.02,1526.64 h60
  text "UL 94V-0" at 11822.96,1526.64 h60
  text "X" at 12498.02,1526.64 h60
  text "RoHS" at 12634.96,1526.64 h60
  text "OTHER" at 13279.36,1526.64 h60
  text "PER ORDER" at 13676.42,1526.64 h60
  text "ADDITIONAL REQUIREMENTS:" at 11332.46,1385.64 h60
  text "MICROSECTION:" at 11407.23,1270.64 h60
  text "YES" at 12312.96,1270.64 h60
  text "REQUIRED" at 13174.46,1114.49 h60
  text "BARE BOARD ELEC. TEST:" at 11407.23,1111.64 h60
  text "NONE" at 12712.96,1111.64 h60
  text "PER ORDER" at 13766.46,1111.64 h60
  text "X" at 12585,1105 h60
  text "MANUFACTURER'S UL:" at 11407.23,954.64 h60
  text "RAIL" at 12572.96,950.35 h60
  text "METAL" at 13064.77,950.35 h60
  text "X" at 13440,950 h60
  text "SILK" at 13576.46,950.35 h60
  text ".Layer_Name" at 577,-858.49 h60
M11 Gerber Information:
  lines w10: -292,-930.17 6308,-930.17 ; -292,-726.83 6310,-726.83 ; -292,-523.5 -292,-1133.5 3713,-1133.5 6310,-1133.5 6310,-523.5 -291.5,-523.5 -291.5,-1133.5 1284,-1133.5 ; 2173,-1133.5 2173,-523.5 ; 3440,-726.83 3440,-523.5 ; 4280,-726.83 4280,-523.5 ; 4902,-1140 4902,-937.17
  text "ALL ARTWORK VIEWED FROM TOP SIDE" at -228.5,-655.67 h60
  text "BOARD #:" at 2248,-655.67 h60
  text ".PRJ_Number" at 2793.5,-655.67 h60
  text "REV:" at 3638,-655.67 h60
  text ".PCB_Rev" at 3929.5,-655.67 h60
  text "SVN REV:" at 4476,-655.67 h60
  text ".VersionControl_RevNumber" at 4982,-655.67 h60
  text "LAYER NAME =" at -228.5,-858.49 h60
  text "PLOT NAME =" at -228.5,-1064.34 h60
  text ".plot_File_Name" at 577,-1064.34 h60
  text "GENERATED    :" at 2250,-1064.34 h60
  text ".Print_Date" at 3119.5,-1064.34 h60
  text ".Print_Time" at 3848.5,-1064.34 h60
  text "TEXAS INSTRUMENTS" at 5113,-1064.34 h60
M12 Stackup:
  lines w6: 11360,7460 13910,7460 ; 11360,7564.4 13910,7564.4 ; 11300,6975 ccw(c11334,6975) 11334,6941 13936,6941 ccw(c13936,6975) 13970,6975 13970,7681 ccw(c13936,7681) 13936,7715 11334,7715 ccw(c11334,7681) 11300,7681 11300,6975
  text "The Stackup Legend below this is static." at 11605.5,7874.5 h60
  text "If you change the stackup, update the Legend." at 11615.5,7784.5 h60
  text "Layer Stack Up Detail for: Ref_Design.PcbDoc" at 11360,7597.1 h57
  text "Layer" at 11360,7525.4 h24
  text "Gerber" at 12255.81,7525.4 h24
  text "Copper" at 12819.33,7525.4 h24
  text "Dielectric" at 13422.04,7525.4 h24
  text "Name" at 11360,7477.4 h24
  text "Document" at 12255.81,7477.4 h24
  text "Thickness" at 12819.33,7477.4 h24
  text "Material" at 13422.04,7477.4 h24
  text "Top Solder Mask" at 11360,7384.44 h34
  text "(.GTS)" at 12255.81,7384.44 h34
  text "Solder Resist" at 13422.04,7384.44 h34
  text "Top Layer" at 11360,7287.69 h34
  text "(.GTL)" at 12255.81,7287.69 h34
  text "1.4mil" at 12819.33,7287.69 h34
  text "FR-4" at 13422.04,7239.31 h34
  text "Bottom Layer" at 11360,7190.94 h34
  text "(.GBL)" at 12255.81,7190.94 h34
  text "1.4mil" at 12819.33,7190.94 h34
  text "Bottom Solder Mask" at 11360,7094.19 h34
  text "(.GBS)" at 12255.81,7094.19 h34
  text "Solder Resist" at 13422.04,7094.19 h34
  text ".Layer_Name" at 577,-858.49 h60
M13 Component Bodies Top:
  text ".Layer_Name" at 577,-858.49 h60
M14 Component Bodies Bottom:
  text ".Layer_Name" at 577,-858.49 h60
M15 Courtyards Top:
  text ".Layer_Name" at 577,-858.49 h60
M16 Courtyards Bottom:
  text ".Layer_Name" at 577,-858.49 h60
Drill Drawing:
  text ".legend" at 2985,215 h60
  text "Drill Table" at 2980,15 h60
  text ".Layer_Name" at 577,-858.49 h60

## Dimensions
0,-410.5 to 1000,-410.5 on M2 Board Dimensions
0,0 to 2750,0 on M2 Board Dimensions
0,0 to 0,2200 on M2 Board Dimensions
